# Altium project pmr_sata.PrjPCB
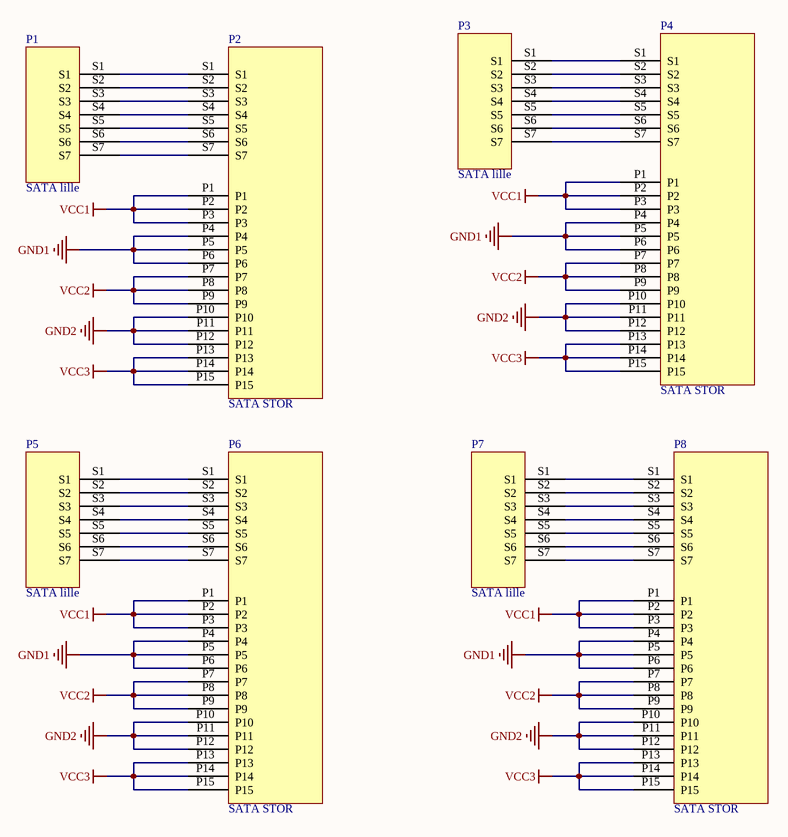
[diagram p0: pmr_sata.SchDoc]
1 sheet, 8 parts. Net scope: global (net labels, ports and power ports of the same name join across sheets).
Board file: pmr_sata2.PcbDoc

## Sheet pmr_sata.SchDoc
size A4

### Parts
P1  SATA lille  [pmr_sata -lille]
P2  SATA STOR  [pmr_sata]
P3  SATA lille  [pmr_sata -lille]
P4  SATA STOR  [pmr_sata]
P5  SATA lille  [pmr_sata -lille]
P6  SATA STOR  [pmr_sata]
P7  SATA lille  [pmr_sata -lille]
P8  SATA STOR  [pmr_sata]

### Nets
GND1: P2.P4 P2.P5 P2.P6 P4.P4 P4.P5 P4.P6 P6.P4 P6.P5 P6.P6 P8.P4 P8.P5 P8.P6
GND2: P2.P10 P2.P11 P2.P12 P4.P10 P4.P11 P4.P12 P6.P10 P6.P11 P6.P12 P8.P10 P8.P11 P8.P12
VCC1: P2.P1 P2.P2 P2.P3 P4.P1 P4.P2 P4.P3 P6.P1 P6.P2 P6.P3 P8.P1 P8.P2 P8.P3
VCC2: P2.P7 P2.P8 P2.P9 P4.P7 P4.P8 P4.P9 P6.P7 P6.P8 P6.P9 P8.P7 P8.P8 P8.P9
VCC3: P2.P13 P2.P14 P2.P15 P4.P13 P4.P14 P4.P15 P6.P13 P6.P14 P6.P15 P8.P13 P8.P14 P8.P15
NetP1_S1: P1.S1 P2.S1
NetP1_S2: P1.S2 P2.S2
NetP1_S3: P1.S3 P2.S3
NetP1_S4: P1.S4 P2.S4
NetP1_S5: P1.S5 P2.S5
NetP1_S6: P1.S6 P2.S6
NetP1_S7: P1.S7 P2.S7
NetP3_S1: P3.S1 P4.S1
NetP3_S2: P3.S2 P4.S2
NetP3_S3: P3.S3 P4.S3
NetP3_S4: P3.S4 P4.S4
NetP3_S5: P3.S5 P4.S5
NetP3_S6: P3.S6 P4.S6
NetP3_S7: P3.S7 P4.S7
NetP5_S1: P5.S1 P6.S1
NetP5_S2: P5.S2 P6.S2
NetP5_S3: P5.S3 P6.S3
NetP5_S4: P5.S4 P6.S4
NetP5_S5: P5.S5 P6.S5
NetP5_S6: P5.S6 P6.S6
NetP5_S7: P5.S7 P6.S7
NetP7_S1: P7.S1 P8.S1
NetP7_S2: P7.S2 P8.S2
NetP7_S3: P7.S3 P8.S3
NetP7_S4: P7.S4 P8.S4
NetP7_S5: P7.S5 P8.S5
NetP7_S6: P7.S6 P8.S6
NetP7_S7: P7.S7 P8.S7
